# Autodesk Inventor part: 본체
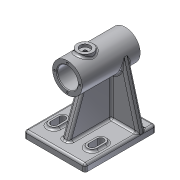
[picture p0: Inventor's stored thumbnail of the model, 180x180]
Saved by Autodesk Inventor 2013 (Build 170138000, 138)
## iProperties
Created: 2019-10
Part Number: 본체
Material: 알루미늄 6061
Document SubType Name: Modeling
Designer: default
Density: 2.71 g/cm^3
Sheet Metal Rule: 기본값
Mass: 590.147 g
Surface Area: 539.917 cm^2
Volume: 217.766 cm^3
Author: default
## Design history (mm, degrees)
sketch "스케치1"
  geometry: L1 (-43, -50)-(43, -50); L2 (43, -50)-(43, 50); L3 (43, 50)-(-43, 50); L4 (-43, 50)-(-43, -50); L5 (-43, -50)-(43, 50); L6 (43, -50)-(-43, 50); 1 further point
  constraints: 12 end point, 2 midpoint, 2 parallel, 1 horizontal, 1 perpendicular
  dimensions: "d0" = 100 distance between parallel lines of L1 L3; "d2" = 86 distance between parallel lines of L4 L2
extrude "돌출1" new body sketch "스케치1" distance "d3" = 10; taper "d4" = 0 deg
sketch "스케치2"
  geometry: L1 (-43, -50)-(43, -50) reference; L2 (43, -50)-(43, 50) reference; L3 (-34, -24)-(-34, -12); L4 (-20, -24)-(-20, -12); L5 (0, 0)-(0, -50); L6 (34, -24)-(34, -12); L7 (20, -24)-(20, -12); A1 r 7 centre (-27, -24) between (-34, -24) and (-20, -24); A2 r 7 centre (-27, -12) between (-20, -12) and (-34, -12); A3 r 7 centre (27, -24) between (20, -24) and (34, -24); A4 r 7 centre (27, -12) between (34, -12) and (20, -12)
  constraints: 10 end point, 8 point on circle, 6 symmetric about line, 4 centre point, 4 tangent, 2 parallel, 1 midpoint, 2 other
  dimensions: "d5" = 14 distance between parallel lines of L4 L3; "d7" = 27 horizontal distance of L5.start A1.centre; "d8" = 26 distance from line of L1 A1.centre; "d9" = 12 distance of A2.centre A1.centre
extrude "돌출2" join sketch "스케치2" distance "d10" = 3; taper "d11" = 0 deg
sketch "스케치3"
  geometry: L1 (-20, -24)-(-20, -12) reference; L2 (0, 0)-(0, -55.2); L3 (-31.5, -12)-(-31.5, -24); L4 (-22.5, -12)-(-22.5, -24); L5 (22.5, -12)-(22.5, -24); L6 (31.5, -12)-(31.5, -24); A1 r 7 centre (-27, -24) between (-34, -24) and (-20, -24) reference; A2 r 7 centre (-27, -12) between (-20, -12) and (-34, -12) reference; A3 r 4.5 centre (-27, -12) between (-22.5, -12) and (-31.5, -12); A4 r 4.5 centre (-27, -24) between (-31.5, -24) and (-22.5, -24); A5 r 4.5 centre (27, -24) between (22.5, -24) and (31.5, -24); A6 r 4.5 centre (27, -12) between (31.5, -12) and (22.5, -12)
  constraints: 10 end point, 8 point on circle, 6 symmetric about line, 4 centre point, 3 parallel, 2 coincident, 2 tangent, 2 other
  dimensions: "d12" = 9 diameter of A3; "d14" = 9 diameter of A4
extrude "돌출3" cut sketch "스케치3" stored distance "d15" = 3; taper "d16" = 0 deg
sketch "스케치4"
  geometry: L1 (86, 32)-(86, -50); L2 (0, 50)-(0, -50) reference; L3 (107, 32)-(100.5, 32); L4 (100.5, 32)-(100.5, -30); L5 (100.5, -30)-(97.5, -30); L6 (97.5, -30)-(97.5, -50); L7 (97.5, -50)-(107, -50); L8 (107, -50)-(107, 32); L9 (0, -50)-(10, -50) reference; 1 further point
  constraints: 14 end point, 4 parallel, 2 perpendicular, 2 point on line, 1 collinear, 1 vertical
  dimensions: "d17" = 86 distance between parallel lines of L2 L1; "d18" = 82 distance between parallel lines of L7 L3; "d19" = 23 diameter of L6 L1; "d20" = 42 diameter of L8 L1; "d21" = 29 diameter of L4 L1; "d71" = 62 distance between parallel lines of L3 L5
revolve "회전1" sketch "스케치4" stored, may be unused: angle "d22" = 90 deg
node "작업 평면1"
fillet "모깎기1" dims "d24" = 3
sketch "스케치7"
  geometry: L1 (22.728, 91.48)-(0.104, 7.783); L2 (63.272, 91.48)-(85.896, 7.783); L3 (3, 10)-(83, 10); A1 r 21 centre (43, 86) between (22.728, 91.48) and (63.272, 91.48) reference; A2 r 3 centre (3, 7) between (3, 10) and (0, 7) reference; A3 r 3 centre (83, 7) between (86, 7) and (83, 10) reference; A4 r 3 centre (3, 7) between (3, 10) and (0.104, 7.783); A5 r 21 centre (43, 86) between (22.728, 91.48) and (63.272, 91.48); A6 r 3 centre (83, 7) between (85.896, 7.783) and (83, 10); 1 further point
  constraints: 8 point on circle, 8 tangent, 6 end point, 3 centre point, 3 concentric, 1 horizontal
extrude "돌출4" join sketch "스케치7" distance "d26" = 10; taper "d27" = 0 deg
sketch "스케치8"
  geometry: L1 (10, 35)-(69, 13.526); L2 (0, 50)-(7, 50) reference; L3 (10, 47)-(10, -25) reference; L4 (10, 35)-(10, -25); L5 (10, -25)-(69, -25); L6 (69, -25)-(69, 13.526); 1 further point
  constraints: 8 end point, 2 perpendicular, 1 collinear, 1 point on line
  dimensions: "d28" = 15 distance from line of L2 L1.start; "d29" = 70 deg angle of L3 L1; "d30" = 59 distance between parallel lines of L6 L3
extrude "돌출5" join sketch "스케치8" stored distance "d31" = 10; taper "d32" = 0 deg
fillet "모깎기3" dims "d34" = 3
node "작업 평면2"
sketch "스케치9"
  geometry: L1 (0, 0)-(0, 32.696); L2 (-21, 32)-(21, 32) reference; C1 r 11 at (0, 7)
  constraints: 2 end point, 1 centre point, 1 point on line, 1 vertical
  dimensions: "d36" = 22 diameter of C1; "d38" = 25 distance from line of L2 C1.centre
extrude "돌출6" join sketch "스케치9" stored distance "d39" = 10; taper "d40" = 0 deg
fillet "모깎기4" dims "d41" = 3
sketch "스케치10" dims "d5" = 14, "d7" = 27, "d8" = 26, "d9" = 12
  geometry: A1 r 11 centre (0, -7) between (0, 4) and (0, -18) reference; 2 further points
  constraints: 1 coincident
hole "구멍1" sketch "스케치10" at (0, -7) diameter "d42" = 4.917; stored, may be unused: countersink angle "d46" = 90 deg, drill point angle "d48" = 118 deg; dims "d43" = 14, "d44" = 14, "d45" = 4, "d47" = 15
chamfer "모따기1" distance "d49" = 1; stored, may be unused: second distance "d50" = 2, angle "d51" = 45 deg
sketch "스케치16" dims "d55" = 36
  geometry: L1 (0, 0)-(0, 18); C1 r 15.5 at (0, 0) reference; 2 further points
  constraints: 2 coincident, 2 end point, 1 vertical, 1 vertical alignment, 2 other
hole "구멍2" sketch "스케치16" at (0, 18) diameter "d57" = 2.459; stored, may be unused: countersink angle "d61" = 90 deg, drill point angle "d63" = 118 deg; dims "d58" = 8, "d59" = 14, "d60" = 4, "d62" = 10
node "작업 평면3"
sketch "스케치17"
  geometry: L1 (40, 50)-(-40, 50) reference; L2 (43, -47)-(43, 47) reference; 2 further points
  constraints: 1 other
  dimensions: "d67" = 7 distance from line of L1 point (0, 43); "d68" = 43 distance from line of L2 point (0, 43)
feature "엠보싱1" sketch "스케치17" dims "d0" = 100, "d2" = 86, "d5" = 14, "d7" = 27, "d8" = 26, "d9" = 12, "d69" = 0.5, "d70" = 0
node "솔리드1"
pattern_circular "원형 패턴1" dims angle "d65" = 360 deg
mirror "대칭1"
other parameters: "d23" = -75
